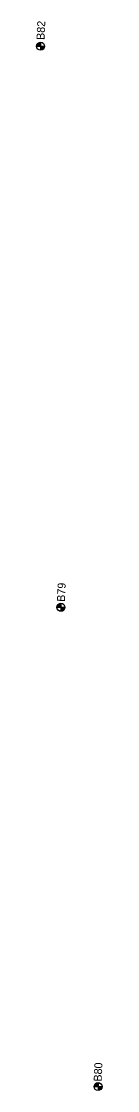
# Model space of a CAD drawing. Extents: x 345549 to 379569, y 127949 to 230467.
# Drawn here: x 360052 to 360135, y 174131 to 175467 of the extents above; entities that cross this region are included whole.
import ezdxf

# ---------------------------------------------------------------- set-up
doc = ezdxf.new("R2010")
doc.units = 0
for name, color, linetype in [('E_SOIL_BORE1 [KAPUR_CADDS_LEVELS]', 7, 'Continuous'), ('E_SOIL_BORE2 [KAPUR_CADDS_LEVELS]', 7, 'Continuous'), ('P_MARK', 7, 'Continuous')]:
    doc.layers.add(name, color=color, linetype=linetype)

msp = doc.modelspace()

# ---------------------------------------------------------------- linework, layer by layer
at = {"layer": 'P_MARK'}
for p, q in [((360052.2, 175435.6), (360062.2, 175435.6)), ((360057.2, 175440.6), (360057.2, 175430.6)), ((360077.6, 174734.7), (360087.6, 174734.7)), ((360082.6, 174739.7), (360082.6, 174729.7)), ((360124, 174136), (360134, 174136)), ((360129, 174141), (360129, 174131))]:
    msp.add_line(p, q, dxfattribs=at)
for centre in [(360057.2, 175435.6), (360082.6, 174734.7), (360129, 174136)]:
    msp.add_circle(centre, 5, dxfattribs=at)
for centre, radius, start, end in [((360057.2, 175435.6), 4.5, 89.9869, 179.9869), ((360057.2, 175435.6), 4, 89.9869, 179.9869), ((360057.2, 175435.6), 3.5, 89.9869, 179.9869), ((360057.2, 175435.6), 3, 89.9869, 179.9869), ((360057.2, 175435.6), 2.5, 89.9869, 179.9869), ((360057.2, 175435.6), 2, 89.9869, 179.9869), ((360057.2, 175435.6), 1.5, 89.9869, 179.9869), ((360057.2, 175435.6), 1, 89.9869, 179.9869), ((360057.2, 175435.6), 0.5, 89.9869, 179.9869), ((360057.2, 175435.6), 4.5, 269.9869, 359.9869), ((360057.2, 175435.6), 4, 269.9869, 359.9869), ((360057.2, 175435.6), 3.5, 269.9869, 359.9869), ((360057.2, 175435.6), 3, 269.9869, 359.9869), ((360057.2, 175435.6), 2.5, 269.9869, 359.9869), ((360057.2, 175435.6), 2, 269.9869, 359.9869), ((360057.2, 175435.6), 1.5, 269.9869, 359.9869), ((360057.2, 175435.6), 1, 269.9869, 359.9869), ((360057.2, 175435.6), 0.5, 269.9869, 359.9869), ((360082.6, 174734.7), 4.5, 89.9869, 179.9869), ((360082.6, 174734.7), 4, 89.9869, 179.9869), ((360082.6, 174734.7), 3.5, 89.9869, 179.9869), ((360082.6, 174734.7), 3, 89.9869, 179.9869), ((360082.6, 174734.7), 2.5, 89.9869, 179.9869), ((360082.6, 174734.7), 2, 89.9869, 179.9869), ((360082.6, 174734.7), 1.5, 89.9869, 179.9869), ((360082.6, 174734.7), 1, 89.9869, 179.9869), ((360082.6, 174734.7), 0.5, 89.9869, 179.9869), ((360082.6, 174734.7), 4.5, 269.9869, 359.9869), ((360082.6, 174734.7), 4, 269.9869, 359.9869), ((360082.6, 174734.7), 3.5, 269.9869, 359.9869), ((360082.6, 174734.7), 3, 269.9869, 359.9869), ((360082.6, 174734.7), 2.5, 269.9869, 359.9869), ((360082.6, 174734.7), 2, 269.9869, 359.9869), ((360082.6, 174734.7), 1.5, 269.9869, 359.9869), ((360082.6, 174734.7), 1, 269.9869, 359.9869), ((360082.6, 174734.7), 0.5, 269.9869, 359.9869), ((360129, 174136), 4.5, 89.9869, 179.9869), ((360129, 174136), 4, 89.9869, 179.9869), ((360129, 174136), 3.5, 89.9869, 179.9869), ((360129, 174136), 3, 89.9869, 179.9869), ((360129, 174136), 2.5, 89.9869, 179.9869), ((360129, 174136), 2, 89.9869, 179.9869), ((360129, 174136), 1.5, 89.9869, 179.9869), ((360129, 174136), 1, 89.9869, 179.9869), ((360129, 174136), 0.5, 89.9869, 179.9869), ((360129, 174136), 4.5, 269.9869, 359.9869), ((360129, 174136), 4, 269.9869, 359.9869), ((360129, 174136), 3.5, 269.9869, 359.9869), ((360129, 174136), 3, 269.9869, 359.9869), ((360129, 174136), 2.5, 269.9869, 359.9869), ((360129, 174136), 2, 269.9869, 359.9869), ((360129, 174136), 1.5, 269.9869, 359.9869), ((360129, 174136), 1, 269.9869, 359.9869), ((360129, 174136), 0.5, 269.9869, 359.9869)]:
    msp.add_arc(centre, radius, start, end, dxfattribs=at)

# ---------------------------------------------------------------- texts
at = {"layer": 'E_SOIL_BORE1 [KAPUR_CADDS_LEVELS]'}
msp.add_text('B80', height=10, rotation=87.2646, dxfattribs=at).set_placement((360133.4, 174142.1))
at = {"layer": 'E_SOIL_BORE2 [KAPUR_CADDS_LEVELS]'}
for s, p in [('B82', (360062, 175443.3)), ('B79', (360087.5, 174741.4))]:
    msp.add_text(s, height=10, rotation=87.2646, dxfattribs=at).set_placement(p)

doc.saveas('drawing.dxf')
